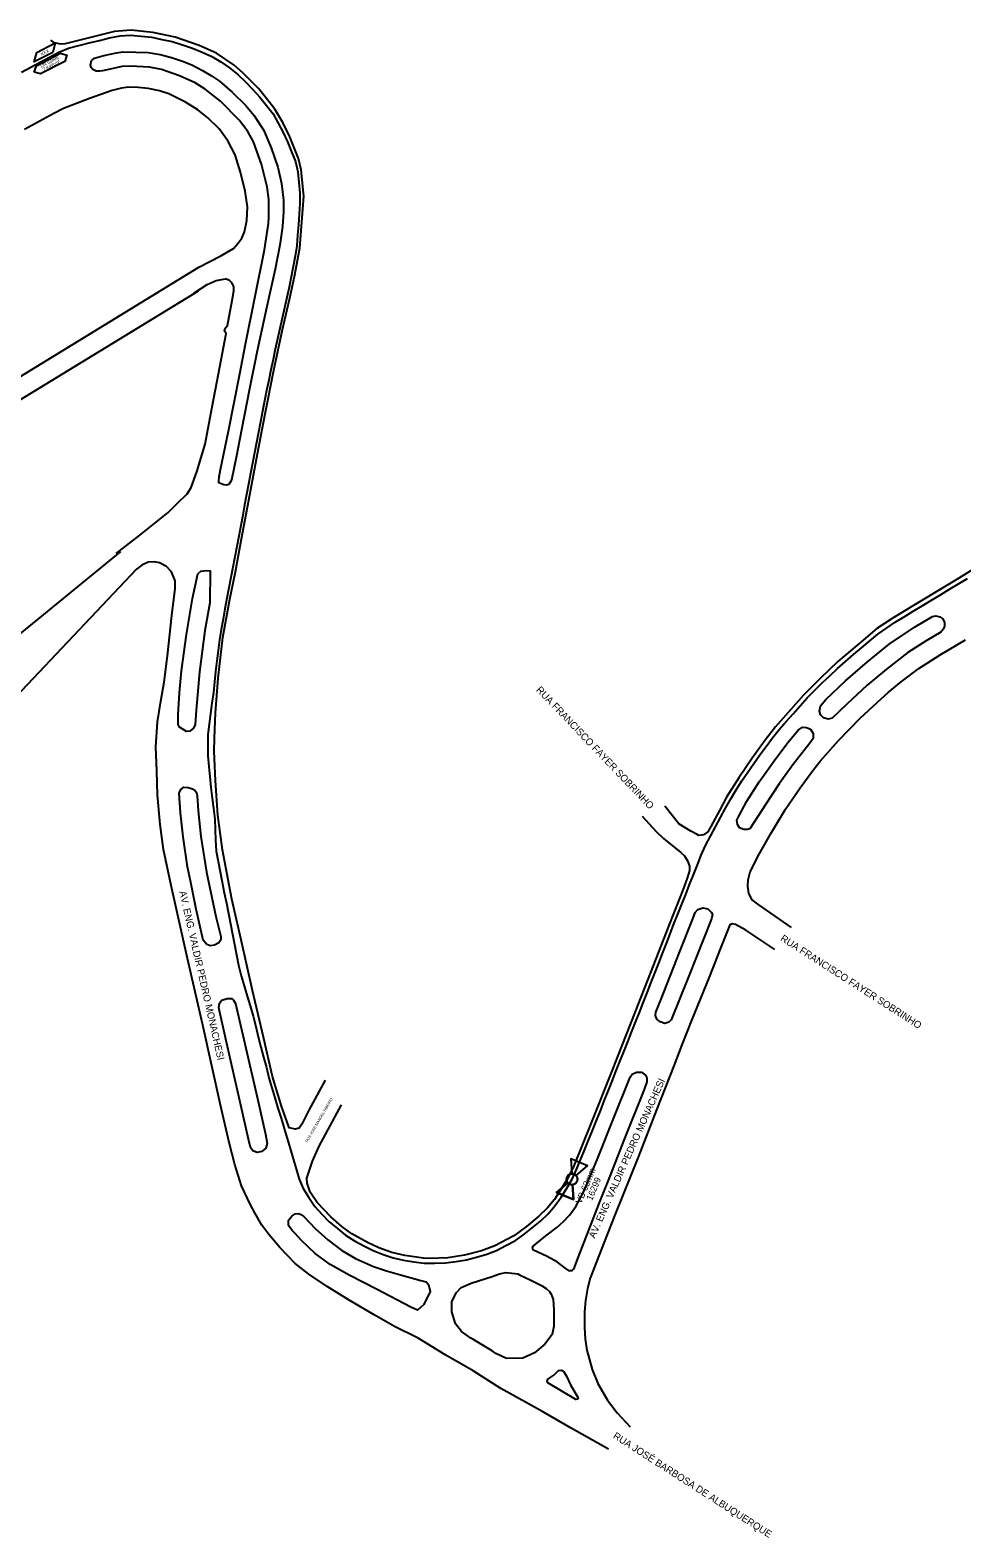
# Model space of a CAD drawing. Extents: x 656692 to 673945, y 7585994 to 7599066.
# Drawn here: x 660694 to 661561, y 7587116 to 7588519 of the extents above; entities that cross this region are included whole.
import ezdxf

# ---------------------------------------------------------------- set-up
doc = ezdxf.new("R2010")
doc.units = 0
for name, color, linetype in [('LOGRADOURO', 7, 'Continuous'), ('LOGRADOURO_TEXTO', 7, 'Continuous'), ('SIMBOLO', 7, 'Continuous'), ('TEXTO', 7, 'Continuous'), ('TUBO_PEAD_GN_63', 7, 'Continuous'), ('VALVULA_PEAD_63', 7, 'Continuous')]:
    doc.layers.add(name, color=color, linetype=linetype)

# ---------------------------------------------------------------- blocks, each defined once
blk = doc.blocks.new('VALVULA_PEAD_DN_9')
at = {"layer": 'VALVULA_PEAD_63'}
for points in [[(-1.14, 0.57), (-4.25, 2.13), (-4.25, -2.13), (-1.14, -0.57)], [(-1.14, -0.57), (-4.25, -2.13), (-4.25, 2.13), (-1.14, 0.57)], [(1.14, -0.57), (4.25, -2.13), (4.25, 2.13), (1.14, 0.57)], [(1.14, -0.57), (4.25, -2.13), (4.25, 2.13), (1.14, 0.57)]]:
    blk.add_lwpolyline(points, dxfattribs=at)
blk.add_circle((0, 0), 1.28, dxfattribs=at)
for start, end in [(90, 270), (153.4349, 206.5651), (270, 90), (0, 26.5651), (333.4349, 0)]:
    blk.add_arc((0, 0), 1.28, start, end, dxfattribs=at)

msp = doc.modelspace()

# ---------------------------------------------------------------- linework, layer by layer
at = {"layer": 'LOGRADOURO'}
for points in [[(660968, 7587542.1), (660952.9, 7587514), (660946.5, 7587501.1), (660943.9, 7587497.3), (660940.5, 7587496.4), (660934.6, 7587497.7), (660927.5, 7587517.7), (660919.1, 7587545.5), (660910.7, 7587582.1), (660900.6, 7587625.4), (660890, 7587672.5), (660881.3, 7587710.5), (660872.5, 7587756.4), (660868.4, 7587788.7), (660866, 7587821), (660865, 7587848), (660865.2, 7587860.2), (660866, 7587883.8), (660868.5, 7587916.1), (660873, 7587953.9), (660879.5, 7587989.8), (660884.6, 7588015.3), (660890.3, 7588045.9), (660897.9, 7588086.9), (660905.2, 7588124.9), (660912.3, 7588162.3), (660920.5, 7588202.9), (660928.5, 7588240.6), (660935, 7588268.7), (660939.6, 7588290.1), (660944.7, 7588316.5), (660948.3, 7588364.8), (660945.8, 7588389.3), (660943.3, 7588399.9), (660935.2, 7588420.2), (660928.6, 7588433.5), (660921.4, 7588446), (660913.7, 7588455.9), (660906, 7588465), (660891.5, 7588479.8), (660883.4, 7588486.7), (660866.9, 7588497.9), (660850.8, 7588505.1), (660828.7, 7588512.8), (660807.9, 7588517.3), (660787.7, 7588519.4), (660772, 7588518.2), (660744.8, 7588511.2), (660726.1, 7588506.6), (660722.1, 7588506.5), (660716.4, 7588507.6), (660712.9, 7588510.1)], [(660760.8, 7588481.6), (660758.6, 7588481.3), (660755.2, 7588481.3), (660752, 7588482.8), (660750.5, 7588484.7), (660749.8, 7588486.9), (660750.8, 7588491.2), (660753.6, 7588493.3), (660762.2, 7588495.8), (660774, 7588498.3), (660780, 7588499.1), (660792.1, 7588499), (660803.4, 7588498.5), (660814.7, 7588496.6), (660825.1, 7588493.9), (660836.4, 7588490.1), (660844.7, 7588486.8), (660853.9, 7588481.9), (660862.3, 7588476.8), (660869.7, 7588471.8), (660881.7, 7588461.7), (660894.2, 7588449.3), (660901.9, 7588440.2), (660910.7, 7588426.5), (660918, 7588410), (660924, 7588391.8), (660927.6, 7588376.8), (660929.3, 7588361.1), (660929.5, 7588350.2), (660928.3, 7588336.7), (660925.9, 7588319.2), (660921.5, 7588296.8), (660913.8, 7588262.3), (660904.6, 7588219.3), (660897.7, 7588185.5), (660890.2, 7588147.3), (660885.5, 7588123), (660881, 7588100.4), (660878.4, 7588096.5), (660876.4, 7588095.8), (660873.9, 7588096.1), (660869.3, 7588097.9), (660869.1, 7588099.3), (660869.4, 7588103.5), (660870.8, 7588110.3), (660878.3, 7588146.2), (660888.7, 7588199.4), (660894.1, 7588227.2), (660903.1, 7588271.7), (660911.7, 7588314.8), (660915.3, 7588339.4), (660915.7, 7588345.3), (660915.7, 7588361.9), (660914.1, 7588373.7), (660908.9, 7588394.8), (660901.3, 7588415.4), (660896.2, 7588425.1), (660888.2, 7588435.6), (660870.6, 7588453.4), (660856.5, 7588464.5), (660847.3, 7588470.5), (660832.6, 7588477), (660815.7, 7588482.7), (660804.7, 7588484.9), (660787, 7588485.8), (660779.4, 7588485.5), (660760.8, 7588481.6)], [(660850.5, 7588298.8), (660871.2, 7588309.3), (660882.9, 7588316.2), (660886.9, 7588320.7), (660890.5, 7588325.9), (660893, 7588331.7), (660895.4, 7588342.1), (660895.8, 7588354.8), (660893.7, 7588369.4), (660889.2, 7588387.3), (660884.5, 7588403.2), (660877.6, 7588416.4), (660869.5, 7588427.5), (660859.1, 7588437.9), (660849.5, 7588445.1), (660838.2, 7588452.5), (660822.8, 7588460), (660814.1, 7588462.8), (660803.3, 7588465.1), (660794.1, 7588466.1), (660785.2, 7588466.4), (660778.7, 7588465.5), (660769.8, 7588463.3), (660749, 7588455.8), (660724.7, 7588446.5), (660715.8, 7588441.8), (660688.5, 7588427)], [(660273.1, 7588136.8), (660342.8, 7588015.2), (660355.1, 7587994.5), (660367, 7588001.9), (660382.6, 7588012.1), (660850.5, 7588298.8)], [(660773.8, 7588032.1), (660795.6, 7588049.3), (660821.9, 7588070.3), (660830.5, 7588078.9), (660839.6, 7588087.8), (660843.6, 7588093.7), (660848.8, 7588108.3), (660856.5, 7588134), (660863.1, 7588168.7), (660868.9, 7588199.4), (660875.9, 7588236.9), (660874.6, 7588239.1), (660875.1, 7588242.1), (660877.2, 7588244.5), (660881.5, 7588267.7), (660883.3, 7588276.6), (660883.1, 7588280.7), (660881.3, 7588284.1), (660879, 7588286.5), (660875.3, 7588287.8)], [(660845.9, 7588274.7), (660858.4, 7588282.5), (660866.7, 7588286.5), (660875.3, 7588287.8)], [(660850.1, 7588276.3), (660362.6, 7587979), (660457.7, 7587772.3), (660777.7, 7588033.7), (660777.7, 7588033.7)], [(660792.5, 7588017.5), (660604.9, 7587819.3), (660367, 7587676.8), (660371.4, 7587655.7), (660494.3, 7587345.3), (660494.3, 7587345.3)], [(660818.4, 7587912.5), (660821.3, 7587936.9), (660825.6, 7587974.6), (660828.5, 7587999.7), (660828.5, 7588006.9), (660825, 7588015.2), (660820.5, 7588020), (660814.1, 7588023.4), (660809, 7588024.6), (660803.3, 7588024.1), (660797.6, 7588021.5), (660792.5, 7588017.5)], [(660849.5, 7588013.4), (660852.5, 7588015.7), (660857.9, 7588016.3), (660861, 7588016.1), (660860.7, 7587986.3), (660856.1, 7587960.6), (660851.1, 7587922.1), (660848, 7587886.4), (660847.2, 7587873), (660845.7, 7587869.7), (660842.2, 7587866.7), (660839, 7587866.6), (660835.1, 7587868.9), (660832.7, 7587870.7), (660831.4, 7587873.2), (660831.4, 7587882.3), (660832.6, 7587902.4), (660834.5, 7587922.9), (660839.1, 7587956.7), (660844.8, 7587990.3), (660849.5, 7588013.4)], [(661578.9, 7588022.2), (661553.6, 7588006.8), (661514.1, 7587983), (661495.7, 7587971.6), (661481.6, 7587962.3), (661468.9, 7587951.5), (661445.3, 7587931.6), (661429, 7587916.1), (661413.1, 7587900.4), (661387.3, 7587871), (661377.6, 7587858.5), (661365.4, 7587841.7), (661352.9, 7587823.3), (661341.7, 7587805.5), (661335.1, 7587793.1), (661327.1, 7587778.2)], [(661533.2, 7587973.7), (661536.5, 7587974.1), (661540.2, 7587973.3), (661542.8, 7587971.4), (661544.5, 7587968), (661544.3, 7587964.7), (661543.5, 7587962.2), (661541.1, 7587959.1), (661527.4, 7587951), (661510.2, 7587940.1), (661490.6, 7587924.6), (661472.6, 7587909.7), (661453.4, 7587892.1), (661440, 7587879.1), (661436.3, 7587878.1), (661431.7, 7587879.4), (661428.9, 7587882.2), (661428.2, 7587885.5), (661428.9, 7587890.3), (661434.1, 7587896.2), (661452.3, 7587913.7), (661472.8, 7587931.5), (661492.8, 7587947.8), (661516.4, 7587963.8), (661533.2, 7587973.7)], [(661402.1, 7587684), (661371.7, 7587705.1), (661365.6, 7587709.7), (661362.5, 7587715.7), (661361.3, 7587722.2), (661361.6, 7587728.3), (661363.7, 7587735.9), (661372, 7587752.2), (661383.3, 7587772.5), (661396.5, 7587794.3), (661410, 7587814.2), (661422, 7587830.1), (661428.8, 7587839), (661445.7, 7587858.2), (661465.9, 7587878.9), (661485.5, 7587897), (661492, 7587902.7), (661504.2, 7587912.8), (661520.6, 7587925.2), (661540.4, 7587937.9), (661564.1, 7587951.8)], [(661231.8, 7587198.4), (661196.9, 7587218.1), (661171.4, 7587232.9), (661131.7, 7587255), (661106, 7587271.4), (661080.3, 7587286.1), (661054.8, 7587301.8), (661032.8, 7587312.7), (661013.8, 7587323.5), (660990.4, 7587337.2), (660970.1, 7587350), (660952.8, 7587361.5), (660940.3, 7587371.4), (660925.9, 7587386.2), (660915.6, 7587398.3), (660909.3, 7587407.1), (660902.7, 7587418.6), (660898.7, 7587425.8), (660890.4, 7587443.5), (660884, 7587463.5), (660878.8, 7587484), (660871.1, 7587517.4), (660854.4, 7587593.2), (660840.1, 7587655.3), (660824.8, 7587723.1), (660817.7, 7587756.7), (660814.5, 7587780), (660812, 7587807.6), (660811.6, 7587829.7), (660810.7, 7587852.2), (660812.1, 7587875.4), (660815.2, 7587894.8), (660818.4, 7587912.5)], [(661363.2, 7587775.8), (661361, 7587775.3), (661357.6, 7587775.4), (661353.8, 7587777), (661351.8, 7587779.9), (661351.2, 7587784), (661352.9, 7587787.8), (661360.4, 7587801.6), (661371.9, 7587819.8), (661385.9, 7587839.3), (661398.7, 7587856.2), (661408.4, 7587867.9), (661412.2, 7587870.5), (661416, 7587870.4), (661419.8, 7587868.6), (661422.1, 7587864.8), (661422.3, 7587859.9), (661419.1, 7587855.6), (661403.4, 7587835.5), (661390.5, 7587817.7), (661378.3, 7587798.8), (661363.2, 7587775.8)], [(660833.6, 7587790.8), (660832.2, 7587809.1), (660833.7, 7587812.4), (660836.7, 7587814.6), (660840.7, 7587814.5), (660844.7, 7587813.3), (660847, 7587811.8), (660848.5, 7587809.6), (660848.9, 7587806.7), (660849.9, 7587792.8), (660852.4, 7587768.7), (660857.8, 7587735.6), (660866.5, 7587694.2), (660870.9, 7587675.8), (660871, 7587672.6), (660869.3, 7587669.7), (660865.3, 7587667.7), (660861.2, 7587667), (660857.9, 7587668.2), (660854.7, 7587672.2), (660848.2, 7587701.3), (660842.9, 7587727.5), (660840.1, 7587740.4), (660836, 7587768.4), (660833.6, 7587790.8)], [(661263.2, 7587787.8), (661276.1, 7587773.4), (661282.9, 7587766.9), (661299, 7587754), (661302.4, 7587750.8), (661305.4, 7587746), (661307.2, 7587741.1), (661307.1, 7587737.1), (661305.4, 7587730.8), (661302, 7587721.2), (661287.9, 7587685.8), (661271, 7587642.1), (661256.4, 7587604.8), (661240.2, 7587564.1), (661235.7, 7587552.9), (661215.1, 7587500.8), (661199.5, 7587462.3), (661194.3, 7587451.3), (661188.2, 7587441), (661181.4, 7587430.9), (661175, 7587423.2), (661167, 7587415.3), (661155.6, 7587405.6), (661143.7, 7587397), (661126, 7587387.6), (661113.7, 7587383.2), (661097.8, 7587379), (661082.2, 7587376.5), (661065.2, 7587375.9), (661059.5, 7587376.3), (661042.3, 7587378.8), (661030.1, 7587381.6), (661018, 7587386), (661007.5, 7587390.8), (660993, 7587398.9), (660983.8, 7587405.7), (660973.3, 7587414.6), (660960.7, 7587428), (660954.1, 7587437.7), (660951.5, 7587446.2), (660951.2, 7587450.6), (660956.4, 7587466.5), (660962.4, 7587480.6), (660983.2, 7587518.9)], [(661327.1, 7587778.2), (661324.3, 7587773.1), (661320.2, 7587770.3), (661315.9, 7587769.7), (661314.2, 7587770.7), (661308.4, 7587773.9), (661297.3, 7587780.5), (661284.2, 7587796.9)], [(661306.2, 7587638.3), (661290.1, 7587598.1), (661287.8, 7587596.1), (661284.3, 7587594.8), (661280, 7587596.2), (661276.7, 7587598.8), (661275.6, 7587602.3), (661275.9, 7587605.2), (661280.7, 7587617.5), (661298.2, 7587661.8), (661310.2, 7587692.2), (661312.5, 7587697.9), (661314.8, 7587700.7), (661319.5, 7587702.4), (661324.1, 7587701.4), (661327.4, 7587698.5), (661328.5, 7587696.1), (661327.5, 7587692), (661306.2, 7587638.3)], [(661386.5, 7587663.6), (661359.6, 7587681.5), (661349.8, 7587686.8), (661347.1, 7587687.4), (661344.6, 7587686.5), (661336, 7587664.9), (661325.6, 7587637.9), (661309.3, 7587598.4), (661299.9, 7587574.7), (661292.7, 7587555.3), (661276.5, 7587514.5), (661259.3, 7587470.3), (661238, 7587417.2), (661227, 7587389.5), (661214.6, 7587357.5), (661212.2, 7587348), (661210.3, 7587336.9), (661209.3, 7587326.3), (661209.4, 7587311.8), (661210.2, 7587301), (661211.7, 7587290.6), (661216.7, 7587272.7), (661222, 7587259.6), (661230.9, 7587244), (661239.9, 7587232.2), (661251.9, 7587219.2)], [(660875.8, 7587580), (660869.1, 7587609.4), (660869.7, 7587613.5), (660872, 7587616.5), (660877, 7587618.1), (660880.9, 7587617.9), (660882.9, 7587616.3), (660884.8, 7587613.2), (660904.8, 7587526), (660912.7, 7587491.8), (660914.1, 7587483.1), (660912.8, 7587478.7), (660909.1, 7587475.6), (660904.8, 7587474.7), (660900.8, 7587476.1), (660898.6, 7587479.2), (660896.7, 7587487), (660889.6, 7587518.8), (660875.8, 7587580)], [(661203.6, 7587377.5), (661199.1, 7587366.1), (661197.7, 7587364.5), (661195.2, 7587364.4), (661191, 7587367.2), (661184.3, 7587372.4), (661174.6, 7587377.8), (661161.9, 7587383.8), (661161.9, 7587383.8), (661161, 7587385.5), (661161.8, 7587387.4), (661173.4, 7587396.9), (661183.7, 7587404.7), (661189.8, 7587410.3), (661195.4, 7587416.3), (661201.4, 7587424.5), (661208.5, 7587437.7), (661221, 7587467.1), (661237.5, 7587508.6), (661252, 7587544.9), (661253.8, 7587547.5), (661257.8, 7587549.5), (661262.6, 7587549.4), (661266.3, 7587546.5), (661267.4, 7587544.2), (661267.6, 7587540.3), (661265, 7587533.3), (661246.7, 7587487.6), (661233, 7587452.7), (661222.7, 7587427), (661203.6, 7587377.5)], [(660939.9, 7587399.6), (660937.4, 7587402), (660934.1, 7587406.8), (660934.1, 7587411.5), (660937.4, 7587415.6), (660940.3, 7587417.5), (660943.2, 7587417.7), (660945.5, 7587417), (660948.3, 7587415), (660958.9, 7587403.9), (660970.6, 7587393.4), (660983.7, 7587383.5), (660996.5, 7587376), (661013.1, 7587368.5), (661025.2, 7587364.5), (661038.1, 7587360.6), (661057.2, 7587355.5), (661062, 7587354.3), (661064.3, 7587351.6), (661065.8, 7587345.2), (661059.9, 7587333.2), (661054.2, 7587328), (661048, 7587330.6), (661016, 7587347.4), (660991.1, 7587360), (660972.8, 7587370.4), (660958.9, 7587380.7), (660946.1, 7587392.7), (660939.9, 7587399.6)], [(661104.1, 7587353), (661123.4, 7587359.3), (661130.2, 7587361.7), (661136.4, 7587363), (661147.3, 7587361.6), (661148.9, 7587360.9), (661159.5, 7587355.8), (661169.4, 7587350.7), (661173.7, 7587348), (661176.8, 7587345.3), (661178.3, 7587342.7), (661180.3, 7587337.7), (661180.9, 7587328.3), (661180.8, 7587312.9), (661179.5, 7587305.1), (661172.6, 7587296.2), (661162.9, 7587288.1), (661152, 7587283.2), (661136.9, 7587282.9), (661127, 7587287.6), (661123.6, 7587289.9), (661106.5, 7587300.1), (661103.8, 7587301.7), (661094.9, 7587308), (661089.3, 7587315.1), (661086, 7587326.4), (661086, 7587336), (661090.4, 7587344.3), (661094.8, 7587348.9), (661104.1, 7587353)], [(661203.7, 7587246.3), (661203, 7587244.9), (661201.3, 7587244.8), (661175.3, 7587260.1), (661174.6, 7587261.9), (661175.3, 7587263.7), (661180.8, 7587267.4), (661185.1, 7587271.7), (661188, 7587272.1), (661189.8, 7587271), (661192.6, 7587266.3), (661196.7, 7587257.6), (661203.7, 7587246.3)]]:
    msp.add_lwpolyline(points, dxfattribs=at)
at = {"layer": 'SIMBOLO'}
msp.add_lwpolyline([(660714.6, 7588498.7), (660697.5, 7588489.9), (660699.8, 7588498.6), (660716.8, 7588507.5)], close=True, dxfattribs=at)
msp.add_lwpolyline([(660697.5, 7588480.4), (660699.4, 7588486.3), (660721.8, 7588497.9), (660727.7, 7588496.1), (660725.8, 7588490.2), (660703.4, 7588478.6), (660697.5, 7588480.4)], dxfattribs=at)
at = {"layer": 'TUBO_PEAD_GN_63'}
msp.add_lwpolyline([(660685.7, 7588480.4), (660694.4, 7588485), (660703, 7588489.7), (660711.7, 7588494.3), (660720.4, 7588499), (660729.4, 7588502.7), (660739, 7588505.1), (660748.5, 7588507.5), (660758.1, 7588509.9), (660767.6, 7588512.3), (660777.3, 7588514), (660787.1, 7588514.7), (660796.9, 7588513.8), (660806.7, 7588512.8), (660816.3, 7588510.8), (660825.9, 7588508.8), (660835.3, 7588505.8), (660844.6, 7588502.5), (660853.7, 7588498.9), (660862.7, 7588494.8), (660871.1, 7588489.8), (660879.2, 7588484.3), (660886.9, 7588478.1), (660894, 7588471.3), (660900.9, 7588464.3), (660907.4, 7588456.9), (660913.7, 7588449.3), (660919.6, 7588441.5), (660924.5, 7588432.9), (660929, 7588424.2), (660933.1, 7588415.3), (660936.8, 7588406.1), (660940.4, 7588397), (660942.6, 7588387.4), (660943.6, 7588377.6), (660944.6, 7588367.8), (660944.6, 7588358), (660943.9, 7588348.2), (660943.2, 7588338.4), (660942.5, 7588328.5), (660941.7, 7588318.7), (660940.2, 7588309), (660938.4, 7588299.3), (660936.6, 7588289.7), (660934.5, 7588280.1), (660932.4, 7588270.4), (660930.2, 7588260.8), (660928, 7588251.3), (660925.8, 7588241.7), (660923.7, 7588232), (660921.6, 7588222.4), (660919.6, 7588212.8), (660917.5, 7588203.2), (660915.6, 7588193.5), (660913.6, 7588183.9), (660911.7, 7588174.2), (660909.7, 7588164.6), (660907.9, 7588154.9), (660906, 7588145.2), (660904.2, 7588135.6), (660902.4, 7588125.9), (660900.5, 7588116.2), (660898.7, 7588106.6), (660896.8, 7588096.9), (660895, 7588087.2), (660893.2, 7588077.6), (660891.4, 7588067.9), (660889.6, 7588058.2), (660887.8, 7588048.5), (660886, 7588038.8), (660884.2, 7588029.2), (660882.3, 7588019.5), (660880.5, 7588009.8), (660878.6, 7588000.2), (660876.7, 7587990.5), (660874.9, 7587980.8), (660873.1, 7587971.2), (660871.4, 7587961.5), (660869.7, 7587951.8), (660868.6, 7587942), (660867.4, 7587932.2), (660866.2, 7587922.5), (660865.2, 7587912.7), (660864.1, 7587902.9), (660862.7, 7587893), (660861.4, 7587883.2), (660860.2, 7587873.4), (660859.1, 7587863.6), (660858.9, 7587853.7), (660859.1, 7587843.9), (660860, 7587834), (660860.8, 7587824.2), (660861.9, 7587814.4), (660863.1, 7587804.6), (660864.1, 7587794.8), (660865.4, 7587785), (660865.8, 7587775), (660866.2, 7587765.8), (660866.7, 7587755.1), (660868.6, 7587745.5), (660870.5, 7587735.8), (660872.4, 7587726.2), (660874.3, 7587716.5), (660876.2, 7587706.8), (660878.1, 7587697.2), (660879.9, 7587687.5), (660881.8, 7587677.9), (660883.7, 7587668.2), (660885.6, 7587658.6), (660887.5, 7587648.9), (660889.9, 7587639.2), (660892.7, 7587629.7), (660895.6, 7587620.2), (660898.5, 7587611.1), (660901, 7587601.4), (660903.5, 7587591.9), (660905.9, 7587582.4), (660908.4, 7587572.8), (660910.8, 7587563.3), (660913.4, 7587553.6), (660915.8, 7587544.2), (660918.6, 7587534.8), (660921.4, 7587525.4), (660924.2, 7587515.9), (660927.1, 7587506.5), (660929.9, 7587497.1), (660932.7, 7587487.7), (660935.6, 7587478.2), (660938.4, 7587468.8), (660941.2, 7587459.4), (660944, 7587449.9), (660947.7, 7587441.1), (660952.8, 7587432.6), (660958.4, 7587424.5), (660965.1, 7587417.3), (660972, 7587410.2), (660979.5, 7587403.8), (660987.2, 7587397.8), (660995.5, 7587392.5), (661004.1, 7587387.7), (661012.9, 7587383.4), (661022, 7587379.7), (661031.4, 7587376.6), (661041, 7587374.4), (661050.7, 7587373), (661060.4, 7587371.7), (661070.3, 7587371.5), (661080.1, 7587371.8), (661089.9, 7587373.1), (661099.5, 7587374.7), (661109.1, 7587377.2), (661118.5, 7587380.1), (661127.7, 7587383.5), (661136.4, 7587388.1), (661145.1, 7587392.7), (661153.1, 7587398.4), (661160.9, 7587404.4), (661168.4, 7587410.8), (661175.5, 7587417.6), (661181.9, 7587425), (661187.7, 7587433), (661193.1, 7587441.3), (661197.9, 7587449.8), (661202.1, 7587458.7), (661205.8, 7587467.8), (661209.6, 7587476.9), (661213.3, 7587486.1), (661217, 7587495.2), (661220.6, 7587504.3), (661224.3, 7587513.5), (661227.9, 7587522.6), (661231.5, 7587531.8), (661235.1, 7587540.9), (661238.7, 7587550.1), (661242.4, 7587559.2), (661246, 7587568.4), (661249.7, 7587577.5), (661253.3, 7587586.7), (661256.9, 7587595.8), (661260.6, 7587604.9), (661264.1, 7587614.1), (661267.7, 7587623.3), (661271.3, 7587632.4), (661274.9, 7587641.6), (661278.5, 7587650.8), (661282, 7587660), (661285.6, 7587669.1), (661289.1, 7587678.3), (661292.7, 7587687.5), (661296.3, 7587696.6), (661300, 7587705.8), (661303.6, 7587714.9), (661307.2, 7587724.1), (661310.8, 7587733.2), (661314.5, 7587742.4), (661318.1, 7587751.5), (661322.1, 7587760.5), (661326.8, 7587769.2), (661331.4, 7587777.8), (661336.1, 7587786.5), (661340.7, 7587795.2), (661345.5, 7587803.8), (661350.7, 7587812.2), (661356, 7587820.5), (661361.5, 7587828.6), (661367, 7587836.8), (661372.7, 7587844.8), (661378.5, 7587852.7), (661384.5, 7587860.6), (661390.6, 7587868.3), (661397, 7587875.7), (661403.5, 7587883.1), (661410, 7587890.5), (661416.6, 7587897.8), (661423.6, 7587904.8), (661430.6, 7587911.7), (661437.7, 7587918.5), (661444.8, 7587925.3), (661452.2, 7587931.8), (661459.7, 7587938.1), (661467.3, 7587944.5), (661474.8, 7587950.8), (661482.3, 7587957.2), (661490.4, 7587962.8), (661498.6, 7587968.2), (661507, 7587973.4), (661515.3, 7587978.5), (661523.8, 7587983.6), (661532.2, 7587988.7), (661540.6, 7587993.8), (661549.1, 7587998.9), (661557.5, 7588003.9), (661565.9, 7588009)], dxfattribs=at)

# ---------------------------------------------------------------- block references
at = {"layer": 'VALVULA_PEAD_63', "xscale": 3.9999999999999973, "yscale": 3.9999999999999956, "rotation": 67.16560455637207}
msp.add_blockref('VALVULA_PEAD_DN_9', (661197.9, 7587449.8), dxfattribs=at)

# ---------------------------------------------------------------- texts
for s, p in [('VB 63mm', (661206.4, 7587426.3)), ('16299', (661216.4, 7587429.4))]:
    msp.add_text(s, height=6, rotation=67.1656).set_placement(p)
at = {"layer": 'LOGRADOURO_TEXTO'}
for s, height, rotation, p in [('RUA FRANCISCO FAYER SOBRINHO', 6.562, 313.6208, (661164, 7587904.8)), ('AV. ENG. VALDIR PEDRO MONACHESI', 6.562, 282.8322, (660832.3, 7587717.4)), ('RUA FRANCISCO FAYER SOBRINHO', 6.562, 327.3082, (661391.2, 7587672.3)), ('AV. ENG. VALDIR PEDRO MONACHESI', 6.562, 66.0274, (661219, 7587394.3)), ('RUA JOSÉ MANOEL RIBEIRO', 2.461, 59.7292, (660951.6, 7587483.8)), ('RUA JOSÉ BARBOSA DE ALBUQUERQUE', 6.562, 327.3082, (661235.4, 7587209.2))]:
    msp.add_text(s, height=height, rotation=rotation, dxfattribs=at).set_placement(p)
at = {"layer": 'TEXTO'}
for s, p in [('XXX', (660704.2, 7588495.4)), ('DN 63mm', (660704, 7588484.4)), ('7 Kgf/cm²', (660706.1, 7588481.2))]:
    msp.add_text(s, height=3, rotation=27.3755, dxfattribs=at).set_placement(p)

doc.saveas('drawing.dxf')
